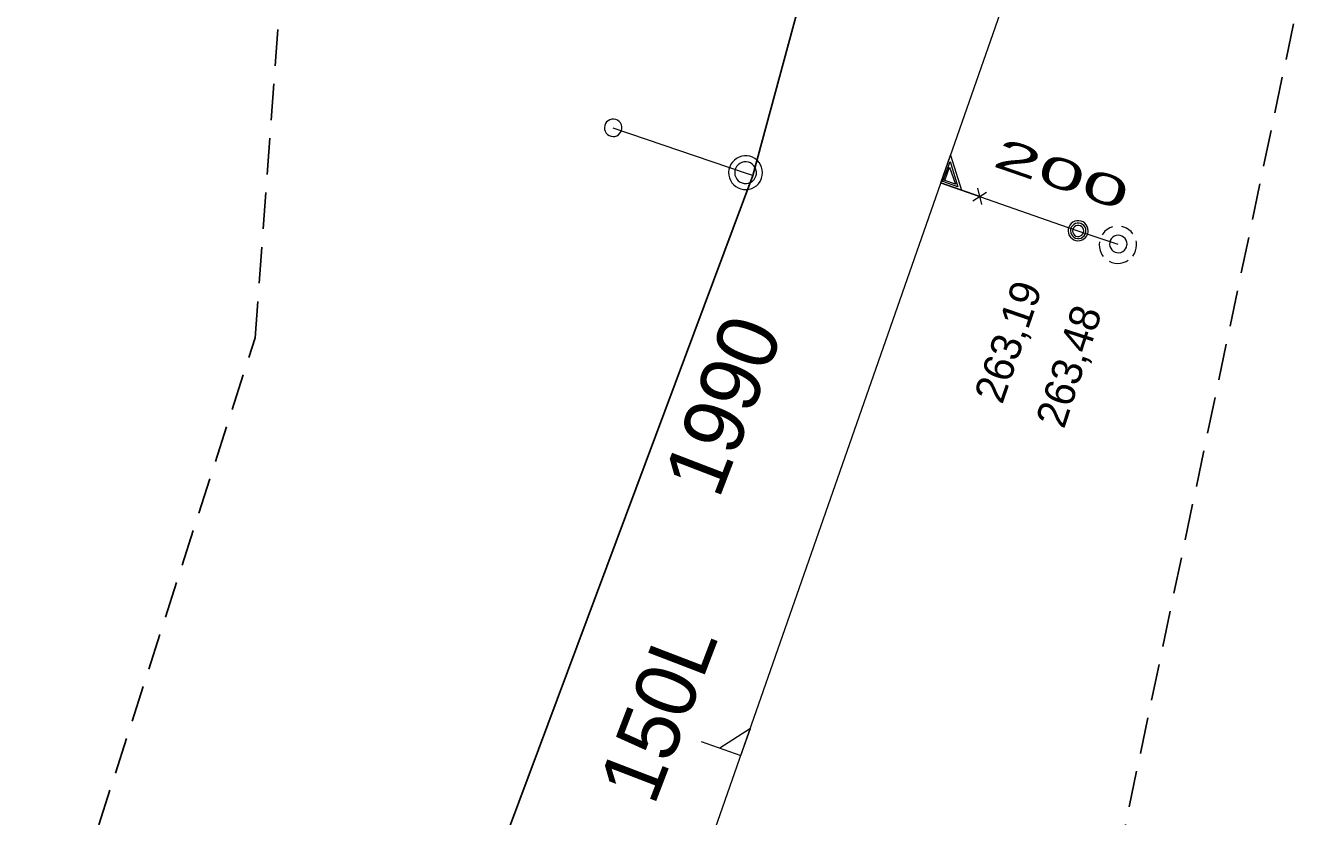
# Model space of a CAD drawing. Extents: x -732074 to -731966, y -1048695 to -1047982.
# Drawn here: x -732037.77 to -732004.31, y -1048216.15 to -1048195.26 of the extents above; entities that cross this region are included whole.
import ezdxf

# ---------------------------------------------------------------- set-up
doc = ezdxf.new("R2010")
doc.units = 0
doc.header["$LTSCALE"] = 0.32
doc.linetypes.add('MEDIUM_DASHED', pattern=[4.5, 3, -1.5])
doc.layers.add('1', color=7, linetype='Continuous')
for name, color, linetype, lineweight in [('18', 7, 'Continuous', 13), ('20', 7, 'Continuous', 13), ('49', 7, 'Continuous', 13), ('63', 7, 'MEDIUM_DASHED', 25), ('8', 7, 'Continuous', 13)]:
    doc.layers.add(name, color=color, linetype=linetype, lineweight=lineweight)

msp = doc.modelspace()

# ---------------------------------------------------------------- linework, layer by layer
at = {"layer": '18'}
for p, q in [((-732012.389, -1048199.668), (-732012.754, -1048199.896)), ((-732012.512, -1048199.983), (-732012.62, -1048199.553))]:
    msp.add_line(p, q, dxfattribs=at)
for points in [[(-732012.564, -1048199.777), (-732013.597, -1048199.415), (-732013.343, -1048198.688), (-732013.052, -1048199.606)], [(-732013.147, -1048199.52), (-732013.539, -1048199.383), (-732013.352, -1048198.848), (-732013.146, -1048199.52)], [(-732013.21, -1048199.448), (-732013.486, -1048199.351), (-732013.363, -1048199), (-732013.211, -1048199.449)], [(-732009.063, -1048200.577), (-732009.134, -1048200.605), (-732009.201, -1048200.644), (-732009.261, -1048200.692), (-732009.312, -1048200.749), (-732009.336, -1048200.783)], [(-732008.522, -1048200.76), (-732008.572, -1048200.702), (-732008.63, -1048200.652), (-732008.695, -1048200.611), (-732008.766, -1048200.582), (-732008.815, -1048200.568)], [(-732009.408, -1048200.969), (-732009.414, -1048201.046), (-732009.409, -1048201.123), (-732009.392, -1048201.198), (-732009.363, -1048201.269), (-732009.323, -1048201.335), (-732009.307, -1048201.357)], [(-732008.527, -1048201.346), (-732008.486, -1048201.281), (-732008.455, -1048201.211), (-732008.436, -1048201.136), (-732008.428, -1048201.06), (-732008.433, -1048200.983), (-732008.439, -1048200.948)], [(-732009.15, -1048201.486), (-732009.08, -1048201.517), (-732009.005, -1048201.536), (-732008.929, -1048201.543), (-732008.852, -1048201.538), (-732008.777, -1048201.521), (-732008.705, -1048201.493), (-732008.645, -1048201.458)], [(-732019.925, -1048214.165), (-732018.875, -1048214.533), (-732018.624, -1048213.815), (-732019.435, -1048214.338)]]:
    msp.add_lwpolyline(points, dxfattribs=at)
for points in [[(-732009.705, -1048200.677), (-732009.711, -1048200.621), (-732009.728, -1048200.568), (-732009.757, -1048200.519), (-732009.795, -1048200.478), (-732009.841, -1048200.446), (-732009.893, -1048200.424), (-732009.948, -1048200.413), (-732010.004, -1048200.415), (-732010.059, -1048200.428), (-732010.11, -1048200.453), (-732010.154, -1048200.488), (-732010.19, -1048200.531), (-732010.215, -1048200.581), (-732010.23, -1048200.636), (-732010.233, -1048200.692), (-732010.224, -1048200.747), (-732010.203, -1048200.8), (-732010.172, -1048200.846), (-732010.132, -1048200.885), (-732010.084, -1048200.915), (-732010.031, -1048200.934), (-732009.975, -1048200.941), (-732009.919, -1048200.937), (-732009.865, -1048200.92), (-732009.816, -1048200.893), (-732009.774, -1048200.855), (-732009.741, -1048200.81), (-732009.718, -1048200.759), (-732009.706, -1048200.704)], [(-732009.764, -1048200.68), (-732009.77, -1048200.631), (-732009.788, -1048200.585), (-732009.816, -1048200.544), (-732009.853, -1048200.511), (-732009.897, -1048200.489), (-732009.945, -1048200.477), (-732009.994, -1048200.477), (-732010.042, -1048200.489), (-732010.086, -1048200.512), (-732010.123, -1048200.545), (-732010.151, -1048200.586), (-732010.168, -1048200.633), (-732010.174, -1048200.682), (-732010.167, -1048200.731), (-732010.149, -1048200.777), (-732010.121, -1048200.817), (-732010.084, -1048200.85), (-732010.04, -1048200.872), (-732009.991, -1048200.884), (-732009.942, -1048200.883), (-732009.894, -1048200.871), (-732009.851, -1048200.847), (-732009.814, -1048200.814), (-732009.786, -1048200.773), (-732009.77, -1048200.726)], [(-732009.823, -1048200.684), (-732009.829, -1048200.642), (-732009.846, -1048200.604), (-732009.874, -1048200.573), (-732009.909, -1048200.55), (-732009.949, -1048200.539), (-732009.991, -1048200.539), (-732010.031, -1048200.551), (-732010.066, -1048200.574), (-732010.093, -1048200.606), (-732010.11, -1048200.644), (-732010.115, -1048200.685), (-732010.109, -1048200.727), (-732010.091, -1048200.764), (-732010.063, -1048200.796), (-732010.027, -1048200.818), (-732009.987, -1048200.829), (-732009.945, -1048200.828), (-732009.905, -1048200.815), (-732009.871, -1048200.792), (-732009.844, -1048200.759), (-732009.828, -1048200.721)], [(-732008.679, -1048201.029), (-732008.685, -1048200.977), (-732008.703, -1048200.927), (-732008.731, -1048200.883), (-732008.769, -1048200.846), (-732008.814, -1048200.819), (-732008.864, -1048200.803), (-732008.916, -1048200.798), (-732008.968, -1048200.805), (-732009.017, -1048200.824), (-732009.061, -1048200.854), (-732009.096, -1048200.893), (-732009.122, -1048200.938), (-732009.137, -1048200.989), (-732009.14, -1048201.041), (-732009.132, -1048201.093), (-732009.111, -1048201.141), (-732009.081, -1048201.184), (-732009.041, -1048201.219), (-732008.995, -1048201.243), (-732008.944, -1048201.257), (-732008.892, -1048201.259), (-732008.84, -1048201.249), (-732008.792, -1048201.227), (-732008.75, -1048201.195), (-732008.717, -1048201.155), (-732008.693, -1048201.108), (-732008.681, -1048201.057)]]:
    msp.add_lwpolyline(points, close=True, dxfattribs=at)
at = {"layer": '20'}
msp.add_lwpolyline([(-732024.989, -1048232), (-732013.598, -1048199.421), (-732011.649, -1048193.85)], dxfattribs=at)
msp.add_lwpolyline([(-732024.989, -1048232), (-732013.598, -1048199.421), (-732011.649, -1048193.85)], dxfattribs=at)
at = {"layer": '49'}
msp.add_line((-732008.91, -1048201.04), (-732009.969, -1048200.69), dxfattribs=at)
msp.add_line((-732008.91, -1048201.04), (-732009.969, -1048200.69), dxfattribs=at)
msp.add_lwpolyline([(-732009.969, -1048200.69), (-732010.428, -1048200.529), (-732013.598, -1048199.421)], dxfattribs=at)
msp.add_lwpolyline([(-732009.969, -1048200.69), (-732010.428, -1048200.529), (-732013.598, -1048199.421)], dxfattribs=at)
at = {"layer": '63'}
for points in [[(-732069.268, -1048320.571), (-732031.703, -1048203.502), (-732026.193, -1048128.486), (-732054.591, -1048051.968)], [(-732014.559, -1048054.287), (-731986.534, -1048110.653), (-731986.533, -1048110.655), (-731986.533, -1048110.657), (-731986.533, -1048110.659), (-732043.346, -1048381.295)]]:
    msp.add_lwpolyline(points, dxfattribs=at)
at = {"layer": '8'}
for p, q in [((-732018.755, -1048199.157), (-732022.252, -1048197.973)), ((-732018.564, -1048199.221), (-732018.755, -1048199.157))]:
    msp.add_line(p, q, dxfattribs=at)
at = {"layer": '8', "lineweight": 25}
msp.add_lwpolyline([(-732017.71, -1048097.66), (-732014.489, -1048102.34), (-732013.919, -1048103.111), (-732010.875, -1048108.055), (-732007.12, -1048116.101), (-732004.818, -1048129.764), (-732005.61, -1048138.74), (-732006.8, -1048149.62), (-732011.172, -1048171.929), (-732011.368, -1048172.669), (-732018.564, -1048199.221), (-732025.78, -1048218.541), (-732027.664, -1048223.962), (-732033.46, -1048240.64)], dxfattribs=at)
at = {"layer": '8'}
for points in [[(-732022.029, -1048198.037), (-732022.018, -1048197.986), (-732022.019, -1048197.932), (-732022.032, -1048197.882), (-732022.056, -1048197.834), (-732022.09, -1048197.794), (-732022.132, -1048197.763), (-732022.18, -1048197.742), (-732022.231, -1048197.732), (-732022.284, -1048197.734), (-732022.335, -1048197.748), (-732022.381, -1048197.774), (-732022.42, -1048197.808), (-732022.45, -1048197.852), (-732022.47, -1048197.9), (-732022.479, -1048197.952), (-732022.474, -1048198.004), (-732022.46, -1048198.054), (-732022.433, -1048198.1), (-732022.397, -1048198.138), (-732022.354, -1048198.168), (-732022.305, -1048198.186), (-732022.252, -1048198.193), (-732022.2, -1048198.188), (-732022.15, -1048198.171), (-732022.106, -1048198.144), (-732022.068, -1048198.107), (-732022.04, -1048198.063)], [(-732018.328, -1048199.29), (-732018.31, -1048199.219), (-732018.304, -1048199.146), (-732018.31, -1048199.073), (-732018.329, -1048199.002), (-732018.357, -1048198.935), (-732018.397, -1048198.874), (-732018.446, -1048198.82), (-732018.504, -1048198.774), (-732018.568, -1048198.739), (-732018.637, -1048198.714), (-732018.709, -1048198.702), (-732018.783, -1048198.701), (-732018.854, -1048198.712), (-732018.924, -1048198.734), (-732018.989, -1048198.768), (-732019.047, -1048198.812), (-732019.098, -1048198.865), (-732019.14, -1048198.925), (-732019.171, -1048198.992), (-732019.19, -1048199.062), (-732019.198, -1048199.135), (-732019.194, -1048199.208), (-732019.178, -1048199.28), (-732019.151, -1048199.347), (-732019.113, -1048199.41), (-732019.065, -1048199.465), (-732019.009, -1048199.512), (-732018.946, -1048199.549), (-732018.877, -1048199.576), (-732018.805, -1048199.591), (-732018.732, -1048199.593), (-732018.66, -1048199.584), (-732018.589, -1048199.563), (-732018.524, -1048199.532), (-732018.464, -1048199.489), (-732018.412, -1048199.438), (-732018.369, -1048199.378), (-732018.337, -1048199.313)], [(-732018.48, -1048199.238), (-732018.467, -1048199.181), (-732018.466, -1048199.123), (-732018.477, -1048199.065), (-732018.499, -1048199.011), (-732018.531, -1048198.962), (-732018.574, -1048198.922), (-732018.623, -1048198.89), (-732018.678, -1048198.869), (-732018.736, -1048198.86), (-732018.795, -1048198.864), (-732018.851, -1048198.878), (-732018.903, -1048198.904), (-732018.949, -1048198.94), (-732018.988, -1048198.985), (-732019.016, -1048199.036), (-732019.033, -1048199.092), (-732019.038, -1048199.151), (-732019.031, -1048199.209), (-732019.012, -1048199.264), (-732018.982, -1048199.315), (-732018.943, -1048199.358), (-732018.896, -1048199.393), (-732018.843, -1048199.417), (-732018.786, -1048199.43), (-732018.728, -1048199.432), (-732018.67, -1048199.421), (-732018.616, -1048199.398), (-732018.568, -1048199.366), (-732018.527, -1048199.324), (-732018.496, -1048199.274)]]:
    msp.add_lwpolyline(points, close=True, dxfattribs=at)

# ---------------------------------------------------------------- texts
at = {"layer": '1', "width": 2.05}
msp.add_text('200 ', height=0.8, rotation=341, dxfattribs=at).set_placement((-732012.263, -1048198.962))
at = {"layer": '1'}
for s, height, rotation, p in [('263,19', 0.8, 71, (-732011.976, -1048205.282)), ('263,48', 0.8, 72, (-732010.344, -1048205.933)), ('1990', 1.6, 69, (-732019.459, -1048207.792)), ('150L', 1.6, 69, (-732021.17, -1048215.886))]:
    msp.add_text(s, height=height, rotation=rotation, dxfattribs=at).set_placement(p)

doc.saveas('drawing.dxf')
